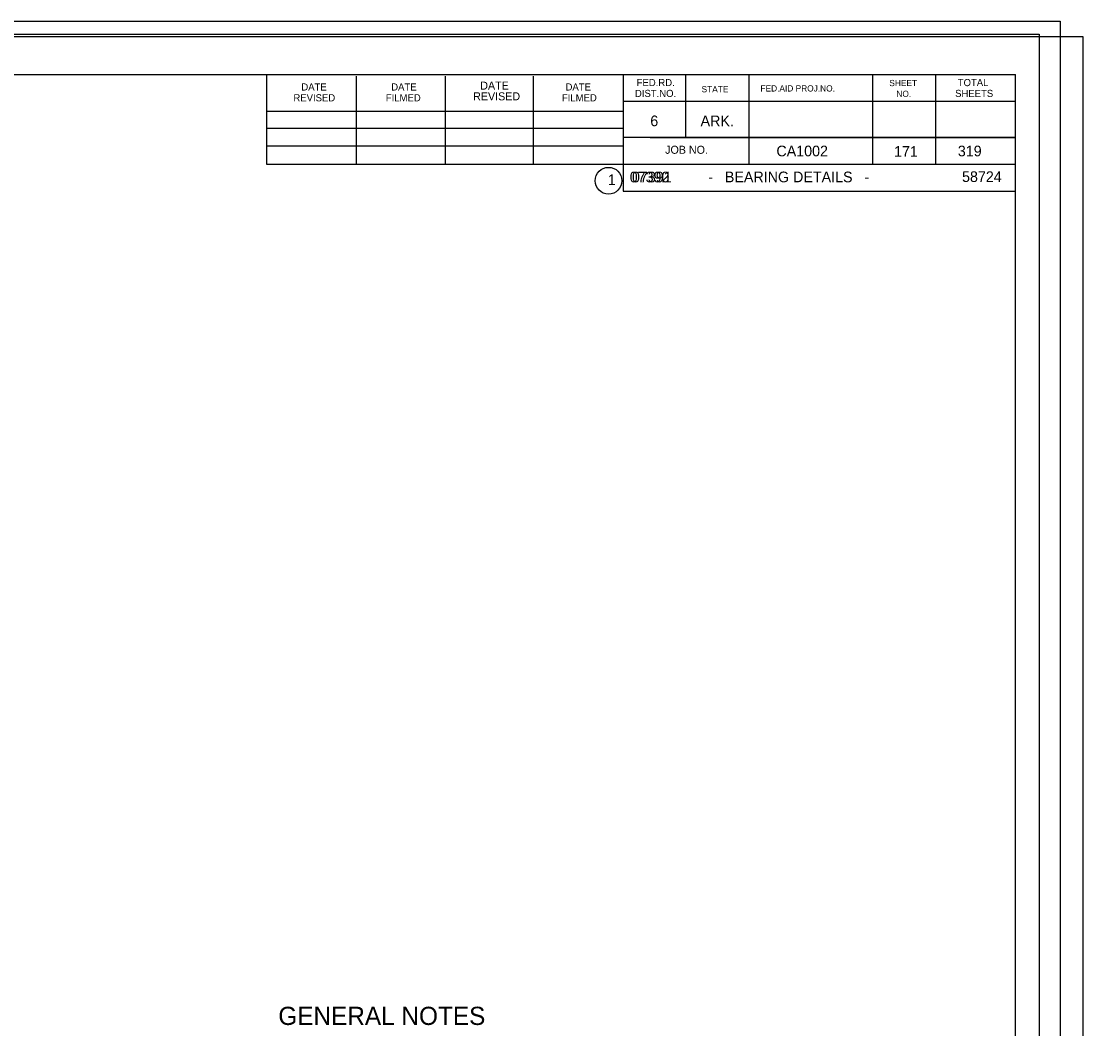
# Model space of a CAD drawing. Extents: x -194 to 226, y 505 to 725.
# Drawn here: x 34.6 to 151.2, y 614.5 to 725.2 of the extents above; entities that cross this region are included whole.
import ezdxf

# ---------------------------------------------------------------- set-up
doc = ezdxf.new("R2010")
doc.units = 0
for name, color, linetype in [('border', 7, 'Continuous'), ('Border 2660-Hwy18 - Level 62', 7, 'Continuous'), ('Border 2660-Hwy18 - Level 63', 7, 'Continuous'), ('Border 2660-Hwy18 - Text', 7, 'Continuous'), ('Bridge No BLFR', 7, 'Continuous'), ('Bridge No BLO', 7, 'Continuous'), ('Bridge No Ditch 81', 7, 'Continuous'), ('Level 41', 7, 'Continuous'), ('Level 62 PDF', 7, 'Continuous'), ('Text', 7, 'Continuous'), ('Title Text', 7, 'Continuous')]:
    doc.layers.add(name, color=color, linetype=linetype)

msp = doc.modelspace()

# ---------------------------------------------------------------- linework, layer by layer
at = {"layer": 'border'}
for p, q in [((-176.33, 719.31), (143.78, 719.31)), ((61.52, 709.44), (61.52, 719.31)), ((71.37, 709.44), (71.37, 719.12)), ((81.14, 709.44), (81.14, 719.12)), ((90.81, 709.44), (90.81, 719.12)), ((100.68, 719.31), (100.68, 706.52)), ((107.52, 719.31), (107.52, 712.38)), ((114.46, 719.31), (114.46, 709.44)), ((128.04, 719.31), (128.04, 709.44)), ((134.98, 719.31), (134.98, 709.44)), ((143.78, 513.86), (143.78, 719.31)), ((143.78, 716.37), (100.68, 716.37)), ((143.78, 716.4), (143.78, 716.4)), ((61.52, 715.29), (100.68, 715.29)), ((61.52, 713.43), (100.68, 713.43)), ((61.52, 709.44), (61.52, 711.5)), ((61.52, 711.5), (100.68, 711.5)), ((143.78, 712.38), (100.68, 712.38)), ((103.64, 712.38), (143.78, 712.38)), ((143.78, 709.44), (61.52, 709.44)), ((100.68, 706.52), (143.78, 706.52))]:
    msp.add_line(p, q, dxfattribs=at)
msp.add_circle((99.06, 707.65), 1.47, dxfattribs=at)
at = {"layer": 'Border 2660-Hwy18 - Level 62'}
msp.add_lwpolyline([(-192.53, 725.17), (148.65, 725.17), (148.65, 507.07), (-192.53, 507.07)], close=True, dxfattribs=at)
at = {"layer": 'Border 2660-Hwy18 - Level 63'}
msp.add_lwpolyline([(-193.64, 723.74), (146.35, 723.74), (146.35, 510.04), (-193.64, 510.04)], close=True, dxfattribs=at)
at = {"layer": 'Level 62 PDF'}
msp.add_lwpolyline([(-190.03, 723.5), (151.15, 723.5), (151.15, 505.41), (-190.03, 505.41)], close=True, dxfattribs=at)

# ---------------------------------------------------------------- texts
at = {"layer": 'Border 2660-Hwy18 - Text'}
for s, height, p in [('DATE', 0.782, (65.32, 717.56)), ('DATE', 0.782, (75.19, 717.56)), ('DATE', 0.879, (84.97, 717.66)), ('DATE', 0.782, (94.34, 717.56)), ('FED.RD.', 0.782, (102.15, 718.04)), ('SHEET', 0.684, (129.9, 718.04)), ('TOTAL', 0.782, (137.42, 718.04)), ('REVISED', 0.782, (64.45, 716.37)), ('FILMED', 0.782, (74.6, 716.37)), ('REVISED', 0.879, (84.19, 716.48)), ('FILMED', 0.782, (93.94, 716.37)), ('DIST.NO.', 0.782, (101.96, 716.85)), ('STATE', 0.684, (109.28, 717.36)), ('FED.AID PROJ.NO.', 0.6839, (115.75, 717.45)), ('NO.', 0.684, (130.68, 716.85)), ('SHEETS', 0.782, (137.13, 716.85)), ('6', 1.17, (103.65, 713.64)), ('ARK.', 1.172, (109.17, 713.64)), ('JOB NO.', 0.879, (105.28, 710.61)), ('CA1002', 1.172, (117.5, 710.33)), ('319', 1.172, (137.43, 710.33)), ('1', 1.17, (98.99, 707.18))]:
    msp.add_text(s, height=height, dxfattribs=at).set_placement(p)
at = {"layer": 'Bridge No BLFR'}
msp.add_text('07392', height=1.172, dxfattribs=at).set_placement((101.39, 707.47))
at = {"layer": 'Bridge No BLO'}
msp.add_text('07391', height=1.172, dxfattribs=at).set_placement((101.64, 707.47))
at = {"layer": 'Bridge No Ditch 81'}
msp.add_text('07390', height=1.172, dxfattribs=at).set_placement((101.39, 707.47))
at = {"layer": 'Level 41'}
msp.add_text('GENERAL NOTES', height=2, dxfattribs=at).set_placement((62.79, 614.92))
at = {"layer": 'Text'}
msp.add_text('171', height=1.172, dxfattribs=at).set_placement((130.42, 710.28))
at = {"layer": 'Title Text'}
for s, height, p in [('-   BEARING DETAILS   -', 1.1722, (110.01, 707.48)), ('58724', 1.172, (137.89, 707.51))]:
    msp.add_text(s, height=height, dxfattribs=at).set_placement(p)

doc.saveas('drawing.dxf')
